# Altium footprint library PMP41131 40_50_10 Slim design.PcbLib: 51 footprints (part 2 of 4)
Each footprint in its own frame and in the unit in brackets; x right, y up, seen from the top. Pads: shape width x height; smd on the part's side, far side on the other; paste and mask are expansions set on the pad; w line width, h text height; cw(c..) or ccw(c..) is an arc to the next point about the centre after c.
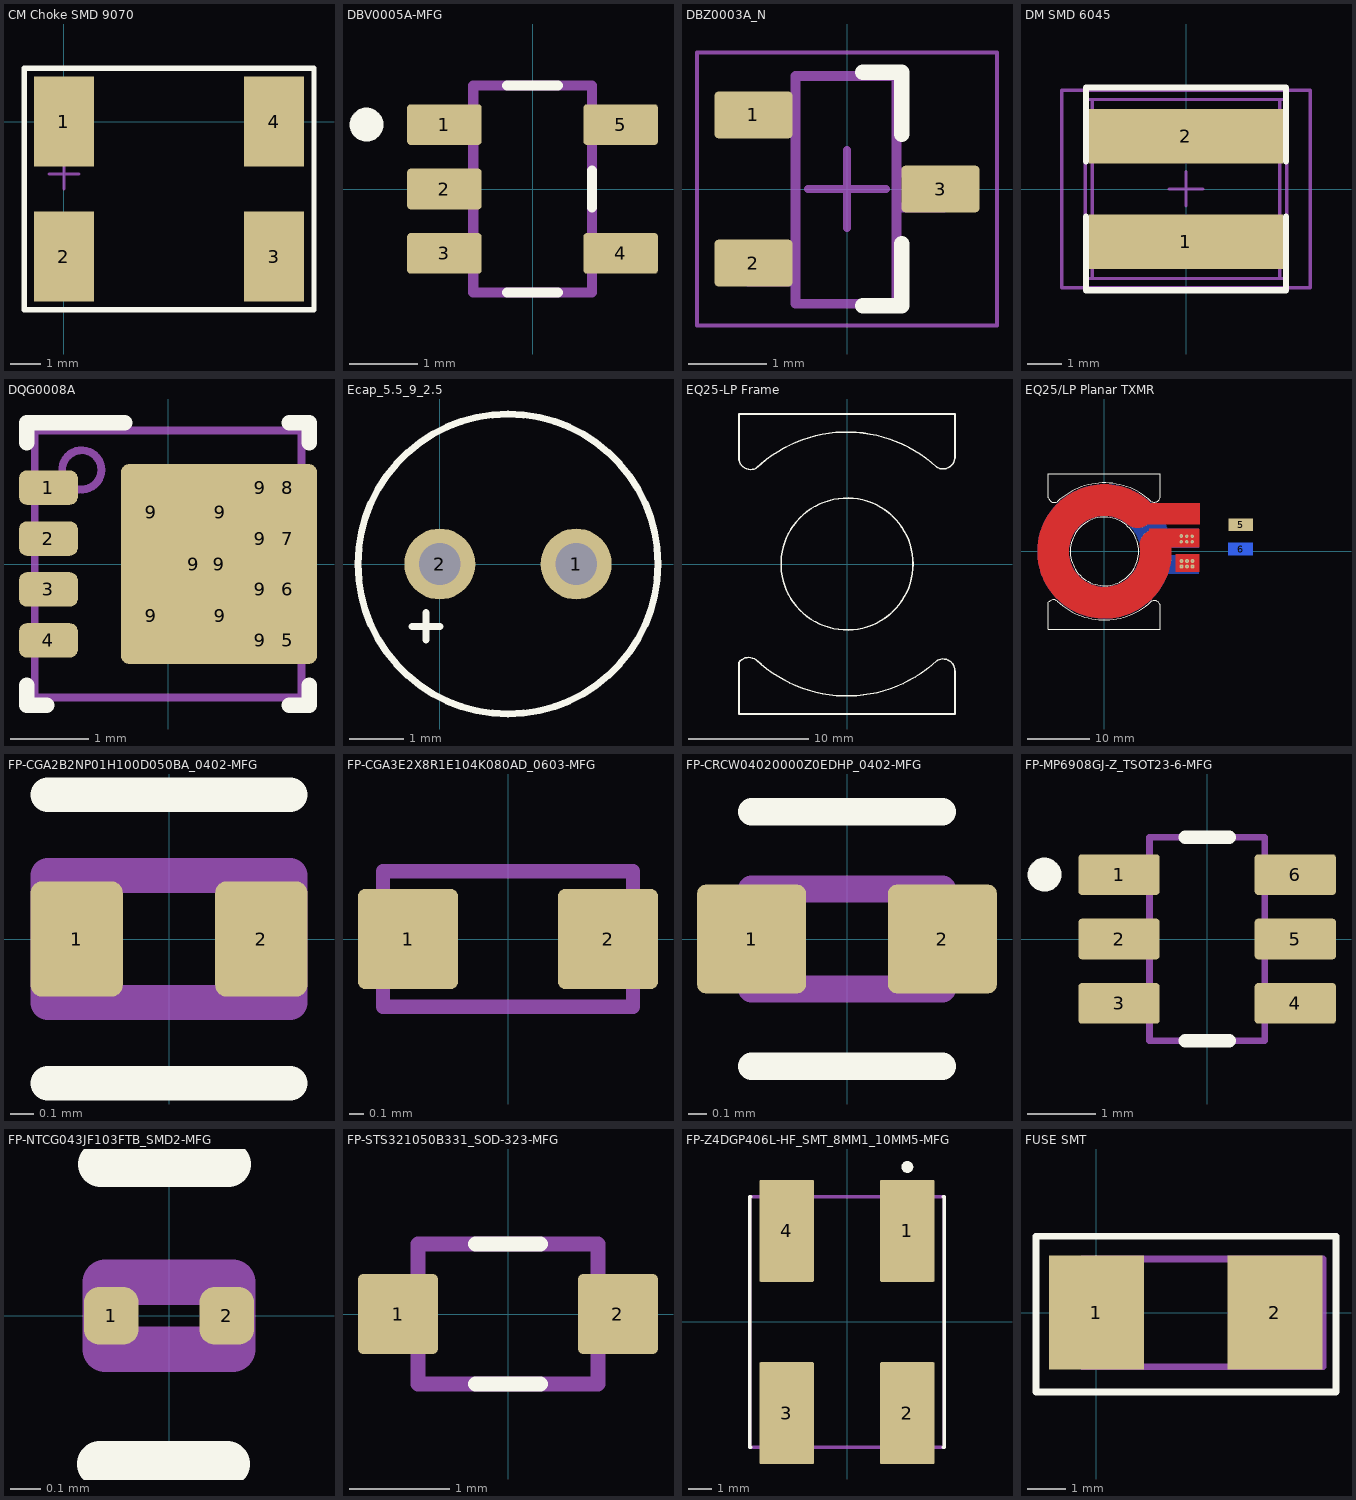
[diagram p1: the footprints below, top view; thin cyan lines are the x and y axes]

## CM Choke SMD 9070 [mm] "Chip Capacitor, Body 5.7x5.0mm, IPC Medium Density"
height 2.8
pads (4):
  rect 2x3 smd: 1(0,0) 2(0,-4.5) 3(7,-4.5) 4(7,0)
Top Overlay:
  lines w0.178: -1.321,-6.27 8.331,-6.27 8.331,1.778 -1.321,1.778 -1.321,-6.27
Mechanical 5:
  text ".Designator" at -1.27,2.743 h1.02
Mechanical 15:
  lines w0.1: -0.5,-1.75 0.5,-1.75 ; 0,-2.25 0,-1.25

## DBV0005A-MFG [mm]
height 1.1
pads (5):
  rrect17% 1.1x0.6 smd paste+0 mask+0: 1(-1.3,0.95) 2(-1.3,0) 3(-1.3,-0.95) 4(1.3,-0.95) 5(1.3,0.95)
Top Overlay:
  circle w0.25: c-2.45,0.95 r0.125
  lines w0.15: -0.375,-1.525 0.375,-1.525 ; -0.375,1.525 0.375,1.525 ; 0.875,-0.275 0.875,0.275
Mechanical 5:
  lines w0.15: -0.875,-1.525 0.875,-1.525 0.875,1.525 -0.875,1.525 -0.875,-1.525
  text ".Designator" at 0.05,0.217 h0.5
3D body "IC_TLV709A33DBVR_SOT23-5.STEP": height 0.25, standoff 0, extent -1.95,-1.775 1.95,1.775

## DBZ0003A_N [mm] "SOT23, 3-Leads, Body 2.9x1.3mm, Pitch 0.95mm, Lead Span 2.4mm, IPC Medium Density"
height 1.12
pads (3):
  rrect17% 1x0.6 smd: 1(-1.2,0.95) 2(-1.2,-0.95) 3(1.2,0)
Top Overlay:
  lines w0.2: 0.2,-1.5 0.7,-1.5 0.7,-0.7 ; 0.2,1.5 0.7,1.5 0.7,0.7
Mechanical 5:
  lines w0.127: -1.27,-1.187 -1.063,-1.187 -1.005,-1.187 -0.814,-1.187 -0.66,-1.187 -0.66,-0.743 -0.814,-0.743 -1.005,-0.743 -1.063,-0.743 -1.27,-0.743 -1.27,-1.187 ; -1.27,0.718 -1.063,0.718 -1.005,0.718 -0.814,0.718 -0.66,0.718 -0.66,1.162 -0.814,1.162 -1.005,1.162 -1.063,1.162 -1.27,1.162 -1.27,0.718 ; -0.66,-1.473 0.635,-1.473 0.635,1.448 -0.66,1.448 -0.66,-1.473 ; 0.635,-0.235 0.635,0.21 0.789,0.21 0.98,0.21 1.037,0.21 1.245,0.21 1.245,-0.235 1.037,-0.235 0.98,-0.235 0.789,-0.235 0.635,-0.235
  text ".Designator" at -0.254,0.889 h0.51
Mechanical 15:
  lines w0.05: -1.925,-1.75 -1.925,1.75 1.925,1.75 1.925,-1.75 -1.925,-1.75
  lines w0.1: -0.5,0 0.5,0 ; 0,-0.5 0,0.5
3D body "DBZ0003A.stp": height 0.98, standoff 0, extent -1.257,-1.461 1.258,1.461

## DM SMD 6045 [mm] "Chip Capacitor, Body 5.7x5.0mm, IPC Medium Density"
height 2.8
pads (2):
  rect 5.7x1.6 smd: 1(0,-1.55) 2(0,1.55)
Top Overlay:
  lines w0.178: -2.939,-0.811 -2.939,-2.97 2.939,-2.97 2.939,-0.811 ; -2.939,0.811 -2.939,2.98 2.939,2.98 2.939,0.811
Mechanical 5:
  lines w0.1: -2.95,-2.625 2.95,-2.625 2.95,2.625 -2.95,2.625 -2.95,-2.625
  text ".Designator" at -1.875,-0.5 h1.02
Mechanical 13:
  lines w0.1: -2.75,-2.625 -2.75,2.625 ; 2.75,-2.625 2.75,2.625 ; -2.95,-2.625 -2.95,2.625 2.95,2.625 2.95,-2.625 -2.95,-2.625
Mechanical 15:
  lines w0.1: -0.5,0 0.5,0 ; 0,-0.5 0,0.5 ; -3.65,-2.9 -3.65,2.9 3.65,2.9 3.65,-2.9 -3.65,-2.9
3D body: height 2.8, standoff 0, extent -2.949,-2.624 -2.751,2.624
3D body: height 2.8, standoff 0, extent -2.749,-2.624 2.749,2.624
3D body: height 2.8, standoff 0, extent 2.751,-2.624 2.949,2.624

## DQG0008A [mm] "SMD, 8-Leads, Body 3.3x3.3mm, Pitch 0.65mm"
height 1.1
pads (18):
  rrect45% 0.75x0.44 smd paste-0.05 mask-0.05: 1(-1.525,0.975) 2(-1.525,0.325) 3(-1.525,-0.325) 4(-1.525,-0.975) 5(1.525,-0.975) 6(1.525,-0.325) 7(1.525,0.325) 8(1.525,0.975)
  rrect50% 0.676x1.125 on Top Paste: 9(-0.212,-0.663) 9(-0.212,0.662) 9(0.664,-0.663) 9(0.664,0.662)
  rrect50% 1.775x2.45 on Top Solder: 9(0.327,0)
  rrect8% 2.5x2.55 smd paste-1.5 mask-1.5: 9(0.65,0)
  rrect50% 0.5x0.34 on Top Solder: 9(1.175,-0.975) 9(1.175,-0.325) 9(1.175,0.325) 9(1.175,0.975)
Top Overlay:
  lines w0.2: -1.8,-1.55 -1.8,-1.8 -1.55,-1.8 ; -1.8,1.55 -1.8,1.8 -0.55,1.8 ; 1.55,-1.8 1.8,-1.8 1.8,-1.55 ; 1.55,1.8 1.8,1.8 1.8,1.55
Mechanical 5:
  circle w0.1: c-1.1,1.2 r0.25
  lines w0.1: -1.7,-1.7 1.7,-1.7 1.7,1.7 -1.7,1.7 -1.7,-1.7
  text ".Designator" at -1.524,-0.508 h0.76
3D body "DQG0008A.stp": height 1.1, standoff 0, extent -1.65,-1.65 1.65,1.65

## Ecap_5.5_9_2.5 [mm]
height 1.1
pads (2):
  round 1.3 hole 0.762: 1(2.5,0) 2(0,0)
Top Overlay:
  circle w0.127: c1.25,0 r2.75
  lines w0.127: -0.508,-1.143 0,-1.143 ; -0.254,-1.397 -0.254,-0.889

## EQ25-LP Frame [mm]
Top Overlay:
  circle w0.127: c0,0 r5.5
  circle w0.127: c0,0 r5.5
  lines w0.127: -9.003,8.651 ccw(c-8.027,8.868) -7.575,7.976 cw(c0,0) 7.468,8.077 ; -9,-8.186 -9,-12.5 0,-12.5 9,-12.5 9,-8.92 ccw(c8.001,-8.91) 7.506,-8.041 cw(c0,0) -7.578,-7.974 ; -9,8.651 -9,12.5 0,12.5 9,12.5 9,8.795 ; -8.992,-8.186 cw(c-8.19,-8.784) -7.589,-7.985 ; 7.449,8.089 ccw(c8,8.923) 8.992,8.795

## EQ25/LP Planar TXMR [mm]
pads (2):
  rect 4x2 smd: 5(21.89,4.27)
  rect 4x2 smd far side: 6(21.86,0.37)
via 14.1,1.55 diameter 0.61 hole 0.203
via 13.22,1.55 diameter 0.61 hole 0.203
via 12.33,1.57 diameter 0.61 hole 0.203
via 14.1,2.44 diameter 0.61 hole 0.203
via 13.22,2.44 diameter 0.61 hole 0.203
via 12.33,2.46 diameter 0.61 hole 0.203
via 14.16,-2.44 diameter 0.61 hole 0.203
via 13.28,-2.44 diameter 0.61 hole 0.203
via 12.39,-2.42 diameter 0.61 hole 0.203
via 14.16,-1.55 diameter 0.61 hole 0.203
via 13.28,-1.55 diameter 0.61 hole 0.203
via 12.39,-1.53 diameter 0.61 hole 0.203
Top Layer:
  rectangle: 11.38,0.66 15.23,3.61
  rectangle: 5.76,4.31 15.33,7.75
  rectangle: 7.18,0.6 15.16,3.7
  rectangle: 11.44,-3.33 15.29,-0.38
  lines w5.1: 5.317,6.308 ccw(c0,0) 8.192,0.976
Signal Layer 1:
  lines w5.1: -8.248,0.19 ccw(c0,0) -6.008,5.654
Signal Layer 2:
  lines w0.8: -9.959,1.684 cw(c0,0) -9.117,-4.347 cw(c13.982,-2.021) -8.902,1.886 cw(c0,0) -8.109,-4.13 ; -7.813,2.135 cw(c0,0) -7.108,-3.884 ; -6.708,2.326 cw(c0,0) -6.091,-3.648 ; -5.653,2.291 cw(c0,0) -5.106,-3.337
Signal Layer 3:
  lines w0.8: -9.949,1.741 ccw(c0,0) -9.315,3.904 ; -9.083,0.561 ccw(c0,0) -8.519,3.201 ; -8.031,-1.057 ccw(c0,0) -7.896,1.807 ; -7.078,0.553 cw(c0,0) -6.918,-1.597 ; -6.096,0.225 cw(c0,0) -5.724,-2.108
Signal Layer 4:
  lines w5.1: 5.58,-6.076 cw(c0,0) 8.192,-0.972
Bottom Layer:
  rectangle: 7.32,0.59 15.16,3.69
  rectangle: 7.32,-3.64 15.16,-0.54
  lines w5.1: 7.65,-3.088 cw(c0,0) 7.768,2.778
Top Overlay:
  circle w0.127: c0,0 r5.5
  circle w0.127: c0,0 r5.5
  lines w0.127: -9.003,8.651 ccw(c-8.027,8.868) -7.575,7.976 cw(c0,0) 7.468,8.077 ; -9,-8.186 -9,-12.5 0,-12.5 9,-12.5 9,-8.92 ccw(c8.001,-8.91) 7.506,-8.041 cw(c0,0) -7.578,-7.974 ; -9,8.651 -9,12.5 0,12.5 9,12.5 9,8.795 ; -8.992,-8.186 cw(c-8.19,-8.784) -7.589,-7.985 ; 7.449,8.089 ccw(c8,8.923) 8.992,8.795
3D body: height 0.51, standoff 0, extent -5.5,-5.5 5.5,5.5
3D body: height 0.51, standoff 0, extent -9.003,7.867 9,12.5
3D body: height 0.51, standoff 0, extent -5.5,-5.5 5.5,5.5
3D body: height 0.51, standoff 0, extent -9,-12.5 9.002,-7.781
3D body: height 0.51, standoff 0, extent -9,-12.5 9.002,-7.781

## FP-CGA2B2NP01H100D050BA_0402-MFG [mm]
height 1.1
pads (2):
  rrect25% 0.4x0.5 smd paste+0 mask+0: 1(-0.4,0) 2(0.4,0)
Top Overlay:
  lines w0.15: -0.525,-0.625 0.525,-0.625 ; -0.525,0.625 0.525,0.625
Mechanical 5:
  lines w0.15: -0.525,-0.275 0.525,-0.275 0.525,0.275 -0.525,0.275 -0.525,-0.275
  text ".Designator" at 0.05,0.217 h0.5
3D body "Cap_CGA2B2NP01H100D050BA_0402.STEP": height 0.25, standoff 0, extent -0.7,-0.375 0.7,0.375

## FP-CGA3E2X8R1E104K080AD_0603-MFG [mm]
height 1.1
pads (2):
  rrect14% 0.7x0.7 smd paste+0 mask+0: 1(-0.7,0) 2(0.7,0)
Mechanical 5:
  lines w0.1: -0.875,-0.475 0.875,-0.475 0.875,0.475 -0.875,0.475 -0.875,-0.475
  text ".Designator" at 0,0 h0.5
3D body "Cap_CGA3E2X8R1E104K080AD_0603.STEP": height 0.25, standoff 0, extent -1.15,-0.575 1.15,0.575

## FP-CRCW04020000Z0EDHP_0402-MFG [mm]
height 1.1
pads (2):
  rrect17% 0.6x0.6 smd paste+0 mask+0: 1(-0.525,0) 2(0.525,0)
Top Overlay:
  lines w0.15: -0.525,-0.7 0.525,-0.7 ; -0.525,0.7 0.525,0.7
Mechanical 5:
  lines w0.15: -0.525,-0.275 -0.525,0.275 0.525,0.275 0.525,-0.275 -0.525,-0.275
  text ".Designator" at 0.05,0.217 h0.5
3D body "Res_CRCW04020000Z0EDHP_0402.STEP": height 0.25, standoff 0, extent -0.925,-0.4 0.925,0.4

## FP-MP6908GJ-Z_TSOT23-6-MFG [mm]
height 1.1
pads (6):
  rrect17% 1.2x0.6 smd paste+0 mask+0: 1(-1.3,0.95) 2(-1.3,0) 3(-1.3,-0.95) 4(1.3,-0.95) 5(1.3,0) 6(1.3,0.95)
Top Overlay:
  circle w0.25: c-2.4,0.95 r0.125
  lines w0.2: -0.325,-1.5 0.325,-1.5 ; -0.325,1.5 0.325,1.5
Mechanical 5:
  lines w0.1: -0.85,-1.5 0.85,-1.5 0.85,1.5 -0.85,1.5 -0.85,-1.5
  text ".Designator" at 0,0 h0.5
3D body "IC_MP6908GJ-Z_TSOT23-6.STEP": height 0.25, standoff 0, extent -2,-1.6 2,1.6

## FP-NTCG043JF103FTB_SMD2-MFG [mm]
height 1.1
pads (2):
  rrect56% 0.18x0.19 smd paste+0 mask+0: 1(-0.19,0) 2(0.19,0)
Top Overlay:
  lines w0.15: -0.228,-0.488 0.192,-0.488 ; -0.225,0.5 0.195,0.5
Mechanical 5:
  lines w0.15: -0.21,-0.11 0.21,-0.11 0.21,0.11 -0.21,0.11 -0.21,-0.11
  text ".Designator" at 0.05,0.217 h0.5
3D body "Res_NTCG043JF103FTB_SMD2.STEP": height 0.25, standoff 0, extent -0.38,-0.21 0.38,0.21

## FP-STS321050B331_SOD-323-MFG [mm]
height 1.1
pads (2):
  rrect13% 0.8x0.8 smd paste+0 mask+0: 1(-1.1,0) 2(1.1,0)
Top Overlay:
  lines w0.15: -0.325,-0.7 0.325,-0.7 ; -0.325,0.7 0.325,0.7
Mechanical 5:
  lines w0.15: -0.9,-0.7 -0.9,0.7 0.9,0.7 0.9,-0.7 -0.9,-0.7
  text ".Designator" at 0.05,0.217 h0.5
3D body "Diode_STS321050B331_SOD-323.STEP": height 0.25, standoff 0, extent -1.6,-0.8 1.6,0.8

## FP-Z4DGP406L-HF_SMT_8MM1_10MM5-MFG [mm]
height 1.1
pads (4):
  rrect4% 2.3x4.3 smd paste+0 mask+0: 1(2.55,3.85) 2(2.55,-3.85) 3(-2.55,-3.85) 4(-2.55,3.85)
Top Overlay:
  circle w0.25: c2.55,6.55 r0.125
  lines w0.15: -4.075,-5.3 -4.1,-5.3 -4.1,5.3 -4.075,5.3 ; 4.075,-5.3 4.1,-5.3 4.1,5.3 4.075,5.3
Mechanical 5:
  lines w0.15: -4.1,-5.3 4.1,-5.3 4.1,5.3 -4.1,5.3 -4.1,-5.3
  text ".Designator" at 0.05,0.217 h0.5
3D body "Diode_Z4DGP406L-HF_SMT_8MM1_10MM5.STEP": height 0.25, standoff 0, extent -4.2,-6.1 4.2,6.1

## FUSE SMT [mm]
height 2.84
pads (2):
  rect 2.5x3 smd: 1(0,0) 2(4.7,0)
Top Overlay:
  lines w0.178: -1.59,-2.09 -1.59,2.01 6.31,2.01 6.31,-2.09 -1.59,-2.09
Mechanical 5:
  lines w0.127: -1.59,-2.1 6.31,-2.1 6.31,2.03 -1.59,2.03 -1.59,-2.1
  text ".Designator" at -1.99,2.84 h1.02
Mechanical 13:
  lines w0.178: 0.975,-1.425 0.975,1.415 ; 4.625,-1.425 4.625,1.415 ; -0.375,-1.425 -0.375,1.415 5.975,1.415 5.975,-1.425 -0.375,-1.425
3D body: height 2.84, standoff 0, extent 4.626,-1.424 5.974,1.414
3D body: height 2.84, standoff 0, extent 0.976,-1.424 4.624,1.414
3D body: height 2.84, standoff 0, extent -0.374,-1.424 0.974,1.414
